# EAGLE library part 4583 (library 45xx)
Dual SCHMITT TRIGGER
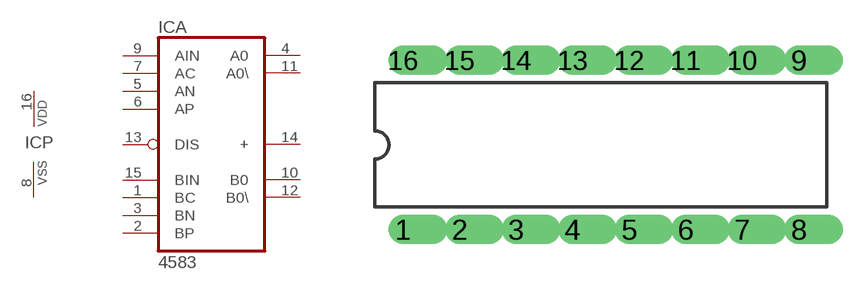
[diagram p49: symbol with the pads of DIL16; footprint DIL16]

Designator prefix IC; gates A=4583 P=PWRN

## 4583N  [DIL16]
1  A:BC  in
2  A:BP  in
3  A:BN  in
4  A:A0  out
5  A:AN  in
6  A:AP  in
7  A:AC  in
8  P:VSS  pwr
9  A:AIN  in
10  A:B0  out
11  A:A0\  out
12  A:B0\  out
13  A:DIS  in
14  A:+  out
15  A:BIN  in
16  P:VDD  pwr

## Footprint DIL16 (pad centres in mm)
Dual In Line
drill 0.813 offset: 1 -8.89,-3.81; 2 -6.35,-3.81; 3 -3.81,-3.81; 4 -1.27,-3.81; 5 1.27,-3.81; 6 3.81,-3.81; 7 6.35,-3.81; 8 8.89,-3.81; 9 8.89,3.81; 10 6.35,3.81; 11 3.81,3.81; 12 1.27,3.81; 13 -1.27,3.81; 14 -3.81,3.81; 15 -6.35,3.81; 16 -8.89,3.81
